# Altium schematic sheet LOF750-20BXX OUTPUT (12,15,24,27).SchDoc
size A4; Revision: A; SheetNumber: 1; SheetTotal: 1
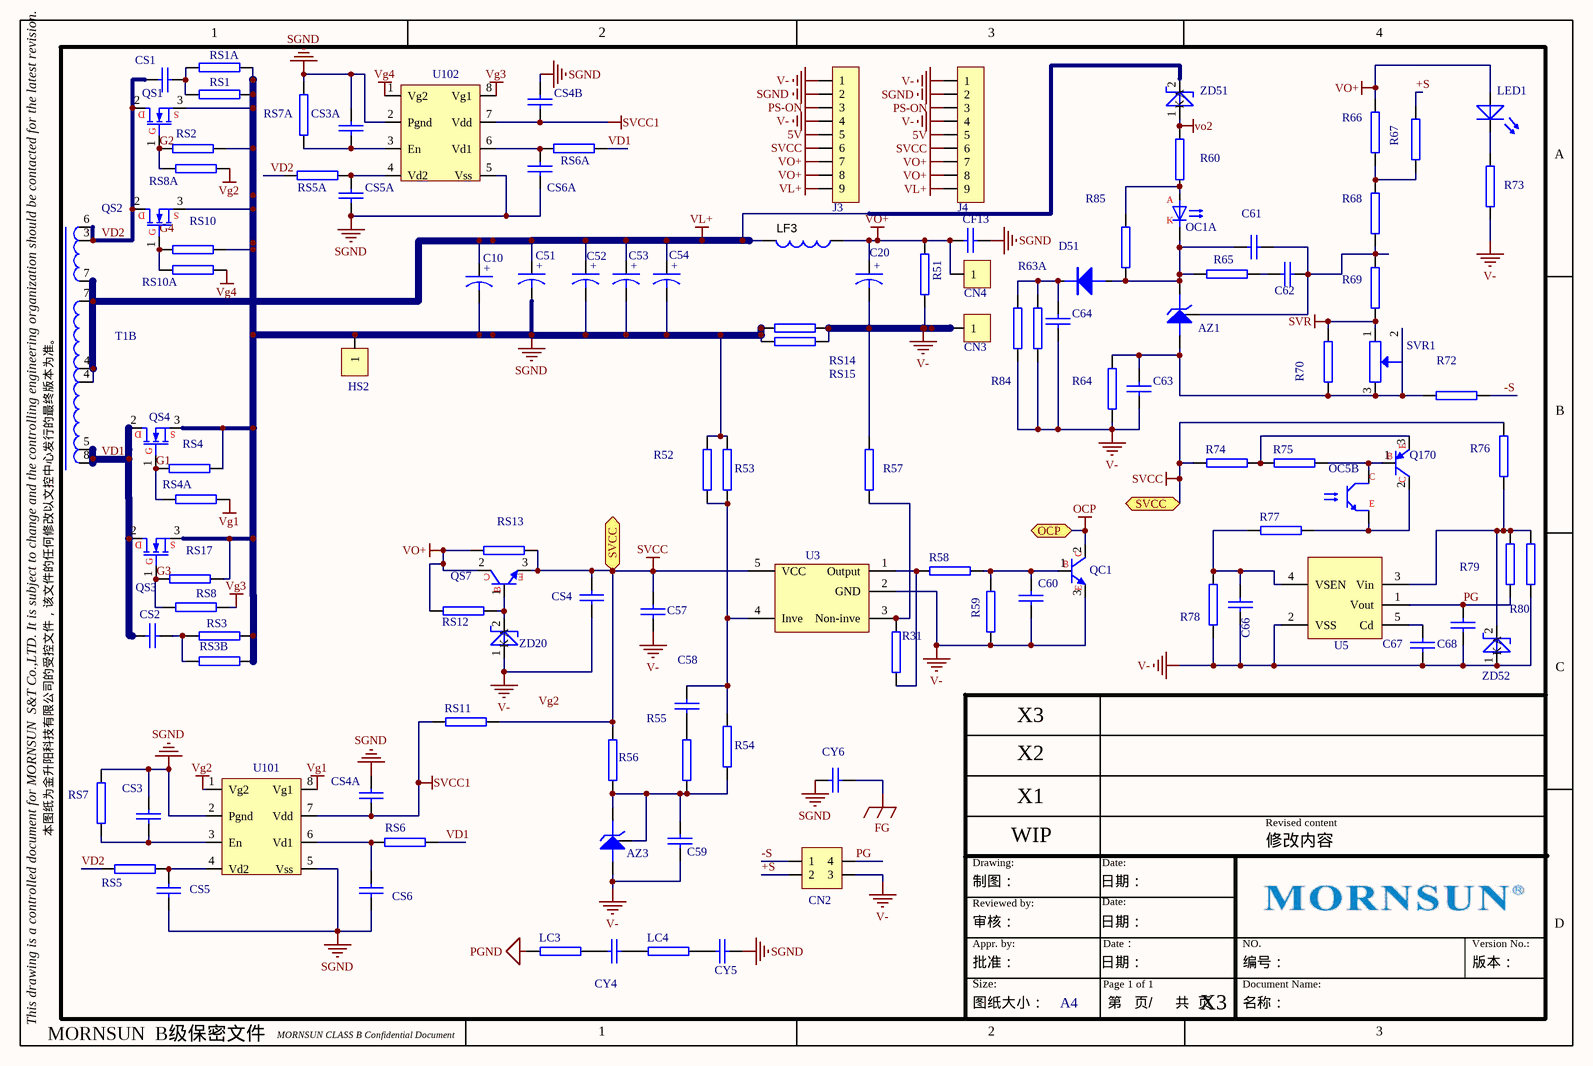
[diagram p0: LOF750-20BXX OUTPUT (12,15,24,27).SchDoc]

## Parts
AZ1  AZ431AN  [SOT-23A]  (value not drawn)
AZ3  AZ431AN/SOT23  [SOT-23A]  (value not drawn)
C10  2200U/16V/10*19/P=5  [EC-3.5-8.0X15.0-V]  (value not drawn)
C20  2200U/16V/10*19/P=5  [EC-3.5-8.0&EC-2.5-6.3]  (value not drawn)
C51  2200U/16V/10*19/P=5  [EC-3.5-8.0X15.0-V]  (value not drawn)
C52  2200U/16V/10*19/P=5  [EC-3.5-8.0X15.0-V]  (value not drawn)
C53  2200U/16V/10*19/P=5  [EC-3.5-8.0X15.0-V]  (value not drawn)
C54  2200U/16V/10*19/P=5  [EC-3.5-8.0X15.0-V]  (value not drawn)
C57  0603  [SC-0603]  (value not drawn)
C58  0603  [SC-0603]  (value not drawn)
C59  0805  [SC-0805]  (value not drawn)
C60  0805  [SC-0805]  (value not drawn)
C61  0603  [SC-0603]  (value not drawn)
C62  0603  [S0603&S0805]  (value not drawn)
C63  0603  [SC-0603]  (value not drawn)
C64  0805  [SC-0805]  (value not drawn)
C66  NC/0603  [SC-0603]  (value not drawn)
C67  0805  [SC-0805]  (value not drawn)
C68  0805  [SC-0805]  (value not drawn)
CF13  0603  [WC-0603]  (value not drawn)
CN2  MHDR1X2  [CON-TJC3-2.0-02P-H(S)]  (value not drawn)
CN3  MHDR1X1  [CON-LOF550-20BXX-8.5]  (value not drawn)
CN4  MHDR1X1  [CON-LOF550-20BXX-8.5]  (value not drawn)
CS1  1206  [SC-1206]  (value not drawn)
CS2  1206  [SC-1206]  (value not drawn)
CS3  0603  [SC-0603]  (value not drawn)
CS3A  0603  [SC-0603]  (value not drawn)
CS4  0805  [SC-0805]  (value not drawn)
CS4A  0805  [SC-0805]  (value not drawn)
CS4B  0805  [SC-0805]  (value not drawn)
CS5  0805  [SC-0805]  (value not drawn)
CS5A  0805  [SC-0805]  (value not drawn)
CS6  0805  [SC-0805]  (value not drawn)
CS6A  0805  [WC-0805]  (value not drawn)
CY4  y1 2n2  [SC-T7-Y1]  (value not drawn)
CY5  y1 2n2  [SC-T7-Y1]  (value not drawn)
CY6  y1 2n2  [CAP-9.5-9.5X7.0-Y]  (value not drawn)
D51  SOD-323  [SOD-323]  (value not drawn)
HS2  MHDR1X1  [750W]  (value not drawn)
J3  MHDR1X9  [CON-2.0-8P-S(插主板)]  (value not drawn)
J4  MHDR1X9  [CON-2.0-8P-S(插小板)]  (value not drawn)
LC3  27k/0603  [SR-0805]  (value not drawn)
LC4  27k/0603  [SR-0805]  (value not drawn)
LED1  LED2  [SLED-0805]  (value not drawn)
LF3  12050306  [750W-L]  (value not drawn)
OC1  OC4  [SOPT-101]  (value not drawn)  (part A of 2)
OC5  OC  [SOPT-101]  (value not drawn)  (part B of 2)
Q170  MMBT2907/SOT-23  [SOT-23A]  (value not drawn)
QC1  SOT23  [SOT-23A]  (value not drawn)
QS1  MOSFET N  [TO220-3]  (value not drawn)
QS2  MOSFET N  [TO220-3]  (value not drawn)
QS3  MOSFET N  [TO220-3]  (value not drawn)
QS4  MOSFET N  [TO220-3]  (value not drawn)
QS7  SOT-89  [SOT-89]  (value not drawn)
R31  56k/0603  [SR-0603]  (value not drawn)
R51  NC/1206  [SR-1206]  (value not drawn)
R52  0603  [SR-0603]  (value not drawn)
R53  0603  [SR-0603]  (value not drawn)
R54  10k/0603  [SR-0603]  (value not drawn)
R55  15k/0603  [SR-0603]  (value not drawn)
R56  3k/0805  [SR-0805]  (value not drawn)
R57  91R/0603  [SR-0603]  (value not drawn)
R58  56k/0603  [SR-0603]  (value not drawn)
R59  33k/0603  [SR-0603]  (value not drawn)
R60  300R/0805  [SR-0805]  (value not drawn)
R63A  10R/0603  [SR-0805]  (value not drawn)
R64  10R/0603  [SR-0603]  (value not drawn)
R65  0603  [SR-0603]  (value not drawn)
R66  100R/0603  [SR-0603]  (value not drawn)
R67  7R5/0805  [SR-0805]  (value not drawn)
R68  0603  [SR-0603]  (value not drawn)
R69  2.4k/0603  [SR-0603]  (value not drawn)
R70  1.3k/0603  [SR-0603]  (value not drawn)
R72  7R5/0603  [SR-0603]  (value not drawn)
R73  7.5k/1206  [SR-1206]  (value not drawn)
R74  5.6K/0805  [SR-0805]  (value not drawn)
R75  5.1k/0603  [SR-0603]  (value not drawn)
R76  1K/1206  [SR-1206]  (value not drawn)
R77  2K/0805  [SR-0805]  (value not drawn)
R78  3K/0603  [SR-0603]  (value not drawn)
R79  100K/0603  [SR-0603]  (value not drawn)
R80  (no value)  [SR-0603]
R84  10R/0603  [SR-0805]  (value not drawn)
R85  2K/0603  [SR-0603]  (value not drawn)
RS1  20R/1206  [SR-1206]  (value not drawn)
RS1A  20R/1206  [SR-1206]  (value not drawn)
RS2  0805  [SR-0805]  (value not drawn)
RS3  20R/1206  [SR-1206]  (value not drawn)
RS3B  20R/1206  [SR-1206]  (value not drawn)
RS4  0805  [SR-0805]  (value not drawn)
RS4A  0603  [SR-0603]  (value not drawn)
RS5  0603  [SR-0603]  (value not drawn)
RS5A  0603  [SR-0603]  (value not drawn)
RS6  0603  [SR-0603]  (value not drawn)
RS6A  0603  [SR-0603]  (value not drawn)
RS7  0603  [SR-0603]  (value not drawn)
RS7A  0603  [SR-0603]  (value not drawn)
RS8  0603  [SR-0603]  (value not drawn)
RS8A  0603  [SR-0603]  (value not drawn)
RS10  0805  [SR-0805]  (value not drawn)
RS10A  0603  [SR-0805]  (value not drawn)
RS11  0805  [SR-0805]  (value not drawn)
RS12  3.9k/0805  [SR-0805]  (value not drawn)
RS13  3.9k/0805  [SR-0805]  (value not drawn)
RS14  1mR/2512  [SR-2512]  (value not drawn)
RS15  1mR/2512  [SR-2512]  (value not drawn)
RS17  0805  [SR-0805]  (value not drawn)
SVR1  1K  [POT-3-5.08-6.6X4.7]  (value not drawn)
T1  PQ3535/开模  [TR-750W-L]  (value not drawn)  (part B of 2)
U3  TS321A1/SOT23-5  [SOT23-5-M]  (value not drawn)
U5  XC6118/SOT-25  [SOT23-5-M]  (value not drawn)
U101  MP6924/TEA2095  [SOP8-1.27]  (value not drawn)
U102  MP6924/TEA2095  [SOP8-1.27]  (value not drawn)
ZD20  SOD-123  [SOD-123&SD-1206]  (value not drawn)
ZD51  SOD-123  [SOD-123&SD-1206]  (value not drawn)
ZD52  SOD123  [SOD-123&SD-1206]  (value not drawn)

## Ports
OCP, SVCC (bidir)

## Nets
5V: J3.5 J4.5
FG: CY6.2
OCP: QC1.2(C) ; port OCP
PGND: LC3.2
PS-ON: J3.3 J4.3
SGND: C10.2 C51.2 C52.2 C53.2 C54.2 CF13.1 CS3.2 CS3A.2 CS4A.1 CS4B.1 CS5.2 CS5A.1 CS6.2 CS6A.1 CY5.1 CY6.1 HS2.1 J3.2 J4.2 QS1.3(S) QS2.3(S) QS3.3(S) QS4.3(S) R52.1 R53.1 RS1.1 RS1A.1 RS2.2 RS3.1 RS3B.1 RS4.2 RS7.2 RS7A.2 RS10.2 RS14.1 RS15.1 RS17.2 U101.2(Pgnd) U101.5(Vss) U102.2(Pgnd) U102.5(Vss)
SVCC: C57.1 CS4.2 J3.6 J4.6 QS7.3(E) R56.1 R74.2 R76.2 RS11.1 RS13.2 U3.5(VCC) ; port SVCC
SVCC1: CS4A.2 CS4B.2 RS11.2 U101.7(Vdd) U102.7(Vdd)
SVR: R69.2 R70.1 SVR1.1
V-: AZ3.2 C20.2 C57.2 C59.1 C60.1 C63.2 C64.2 C66.2 C67.2 C68.2 CN2.3 CN3.1 CS4.1 J3.1 J3.4 J4.1 J4.4 QC1.3(E) R51.2 R57.2 R59.1 R63A.2 R64.2 R73.2 R78.1 R80.2 R84.2 RS14.2 RS15.2 U3.2(GND) U5.2(VSS) ZD20.1(A) ZD52.1(A)
Vg1: RS4A.2 U101.8(Vg1)
Vg2: RS8A.1 U101.1(Vg2)
Vg3: RS8.1 U102.8(Vg1)
Vg4: RS10A.2 U102.1(Vg2)
VL+: C10.1 C51.1 C52.1 C53.1 C54.1 J3.9 J4.9 LF3.0 T1.4 T1.7 ZD51.2(K)
vo2: R60.1 ZD51.1(A)
VO+: C20.1 CF13.2 CN4.1 J3.7 J3.8 J4.7 J4.8 LED1.1(A) LF3.1 QS7.2(C) R51.1 R66.1 RS12.1 RS13.1
+S: CN2.2 R67.2
-S: CN2.1 R72.2
G1: QS4.1(G) RS4.1 RS4A.1
G2: QS1.1(G) RS2.1 RS8A.2
G3: QS3.1(G) RS8.2 RS17.1
PG: C68.1 CN2.4 R79.1 U5.1(Vout)
VD1: CS2.1 QS3.2(D) QS4.2(D) RS6.2 RS6A.1 T1.5 T1.8
VD2: CS1.1 QS1.2(D) QS2.2(D) RS5.1 RS5A.1 T1.3 T1.6
NetAZ1_1: AZ1.1 C61.2 C62.2 R68.2 R69.1
NetAZ1_2: AZ1.2 C63.1 R64.1 R70.2 R72.1 SVR1.2 SVR1.3
NetAZ1_3: AZ1.3 C61.1 D51.1(A) OC1.2(K) R65.1 R85.2
NetAZ3_1: AZ3.1 AZ3.3 C59.2 R54.2 R55.2 R56.2
NetC58_1: C58.1 R52.2 R53.2 R54.1 U3.4(Inve)
NetC58_2: C58.2 R55.1
NetC60_2: C60.2 QC1.1(B) R58.1 R59.2
NetC62_1: C62.1 R65.2
NetC64_1: C64.1 D51.2(K) R63A.1 R84.1
NetC66_1: C66.1 R77.2 R78.2 U5.4(VSEN)
NetC67_1: C67.1 U5.5(Cd)
NetCS1_2: CS1.2 RS1.2 RS1A.2
NetCS2_2: CS2.2 RS3.2 RS3B.2
NetCS3_1: CS3.1 RS7.1 U101.3(En)
NetCS3A_1: CS3A.1 RS7A.1 U102.3(En)
NetCS5_1: CS5.1 RS5.2 U101.4(Vd2)
NetCS5A_2: CS5A.2 RS5A.2 U102.4(Vd2)
NetCS6_1: CS6.1 RS6.1 U101.6(Vd1)
NetCS6A_2: CS6A.2 RS6A.2 U102.6(Vd1)
NetCY4_1: CY4.1 LC4.2
NetCY4_2: CY4.2 LC3.1
NetCY5_2: CY5.2 LC4.1
NetLED1_2: LED1.2(K) R73.1
NetOC1_1: OC1.1(A) R60.2 R85.1
NetOC5_3: OC5.3(E) Q170.2(C) R77.1
NetOC5_4: OC5.4(C) Q170.1(B) R75.1
NetQ170_3: Q170.3(E) R74.1 R75.2
NetQS2_1: QS2.1(G) RS10.1 RS10A.1
NetQS7_1: QS7.1(B) RS12.2 ZD20.2(K)
NetR31_1: R31.1 R57.1 U3.3(Non-inve)
NetR31_2: R31.2 R58.2 U3.1(Output)
NetR66_2: R66.2 R67.1 R68.1
NetR76_1: R76.1 R79.2 R80.1 U5.3(Vin) ZD52.2(K)

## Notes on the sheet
- (near RS1A) 1
- 2
- (near J4) 3
- 4
- A
- B
- X3
- C
- X2
- 本图纸为金升阳科技有限公司的受控文件，该文件的任何修改以文控中心发行的最终版本为准。
- Drawing:
- WIP
- X1
- Date:
- 修改内容
- Revised content
- Reviewed by:
- 审核：
- 制图：
- 日期：
- D
- Appr. by:
- Size:
- 批准：
- Page 1 of 1
- Date：
- Document Name:
- NO.
- 编号：
- Version No.:
- 版本：
- This drawing is a controlled document for MORNSUN  S&T Co.,LTD. It is subject to change and the controlling engineering organization should be contacted for the latest revision.
- MORNSUN  B级保密文件
- MORNSUN CLASS B Confidential Document
- 1
- 图纸大小：
- A4
- 第   页/
- 共  页
- 名称：
- 3
- Labels drawn without touching a wire or pin: G4, Vg2

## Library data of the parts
AZ1 AZ3 = 431: MPN: AZ431AN-ATRE1; PN: 32000001
C10 C20 C51-C54 = CAPACITOR POL: Capacitor; Mfr: Samxon; MPN: ESK228M1VK25RRSRP; APN: 30030042
C57-C64 C66-C68 CF13 CS1-CS3 CS3A CS4 CS4A CS4B CS5 CS5A CS6 CS6A = CAP: 103K/50V/0603/X7R; PN: 30010146
CN2 = Pin2X2
CN3 CN4 HS2 = Pin1
CY4-CY6 = CAP: MPN: YU1AH222M090BAMD0H; PN: 30040010; APN: ??
D51 = DIODE: MPN: SK110; PN: 31000046
J3 J4 = Pin9
LC3 LC4 = RES1: 2.2MΩ 1/8W ±1% 0805
LF3 = 7840-09-0014: PN: 52104014; APN: ??
OC1 = OC
Q170 = PNP: PNP Transistor
QC1 QS7 = NPN: NPN Transistor
R31 R58 R59 = RES1: 2.2MΩ 1/8W ±1% 0805; PN: NC
R51-R57 R60 R63A R64-R70 R72-R80 R84 R85 RS2 RS4 RS4A RS5 RS5A RS6 RS6A RS7 RS7A RS8 RS8A RS10 RS10A RS11 RS14 RS15 RS17 = RES1
RS1 RS1A RS3 RS3B RS12 RS13 = RES1: PN: 35000010
SVR1 = RP: Variable Resistor; Set Position: 0.5
T1 = T
U3 = TS321A1
U5 = XC6118
U101 U102 = MP6922: Mfr: MPS; MPN: MP6922DSE
ZD20 ZD51 ZD52 = Diode 稳压: Zener Diode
